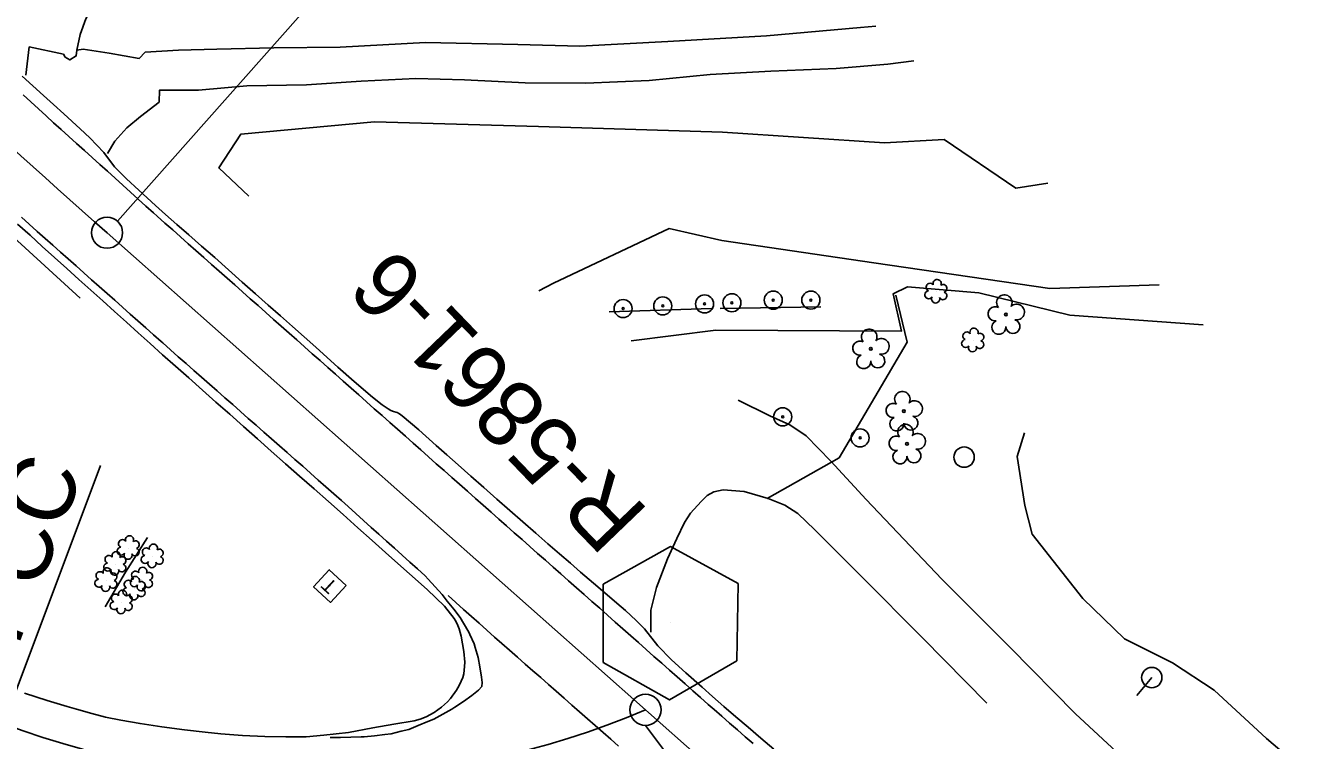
# Model space of a CAD drawing. Extents: x 474972 to 479313, y 498315 to 502691.
# Drawn here: x 476724.1 to 477032.4, y 500512.6 to 500685.1 of the extents above; entities that cross this region are included whole.
import ezdxf

# ---------------------------------------------------------------- set-up
doc = ezdxf.new("R2010")
doc.units = 0
for name, color, linetype in [('CTL Primary Horizontal and Vertical CELL', 7, 'Continuous'), ('CTL Primary Horizontal and Vertical Text', 7, 'Continuous'), ('Exist Guardrail', 7, 'Continuous'), ('Exist Horizontal Alignment', 7, 'Continuous'), ('Exist Other Culture Fence Line', 7, 'Continuous'), ('Exist Other Culture Gate', 7, 'Continuous'), ('Exist Other Culture Sign', 7, 'Continuous'), ('Exist Other Culture Sign Post CELL', 7, 'Continuous'), ('Exist Roads EOP', 7, 'Continuous'), ('Exist Roads EOP Other', 7, 'Continuous'), ('Exist Roads EOT', 7, 'Continuous'), ('Exist Roads Soil', 7, 'Continuous'), ('Exist Utilities Other Located Object CELL', 7, 'Continuous'), ('Exist Utilities Other Pole CELL', 7, 'Continuous'), ('Exist Utilities Power Pole CELL', 7, 'Continuous'), ('Exist Utilities Telephone Pedestal CELL', 7, 'Continuous'), ('Exist Vegetation Hedge Row', 7, 'Continuous'), ('Exist Vegetation Shrub CELL', 7, 'Continuous'), ('Exist Vegetation Tree CELL', 7, 'Continuous'), ('Exist Vegetation Woods Line', 7, 'Continuous')]:
    doc.layers.add(name, color=color, linetype=linetype)

msp = doc.modelspace()

# ---------------------------------------------------------------- linework, layer by layer
at = {"layer": 'CTL Primary Horizontal and Vertical CELL'}
msp.add_line((476879.52, 500540.98), (476879.52, 500540.98), dxfattribs=at)
msp.add_lwpolyline([(476863.36, 500550.34), (476879.61, 500559.4), (476895.86, 500550.46), (476895.61, 500531.84), (476879.36, 500522.4), (476863.36, 500531.46)], close=True, dxfattribs=at)
at = {"layer": 'Exist Guardrail'}
msp.add_lwpolyline([(476737.29, 500619.31), (476708.8, 500645.27), (476684.15, 500668.31), (476658.03, 500693.08), (476634.78, 500715.19), (476612.16, 500736.97), (476592.64, 500756.19), (476581.97, 500766.87)], dxfattribs=at)
at = {"layer": 'Exist Horizontal Alignment'}
for p, q in [((476746.23, 500637.93), (476820.85, 500722.08)), ((477059.47, 500355.18), (476743.74, 500635.12)), ((476720.16, 500520.15), (476742.19, 500578.94)), ((476873.56, 500516.26), (476927.6, 500444.13))]:
    msp.add_line(p, q, dxfattribs=at)
for centre in [(476743.74, 500635.12), (476873.56, 500520.01)]:
    msp.add_circle(centre, 3.75, dxfattribs=at)
for centre, radius, start, end in [((478884.49, 503049.53), 3226.8, 223.91157, 228.4381), ((476791.99, 500711.88), 208.48, 249.4634, 293.0343)]:
    msp.add_arc(centre, radius, start, end, dxfattribs=at)
at = {"layer": 'Exist Other Culture Fence Line'}
msp.add_lwpolyline([(476920.23, 500580.83), (476936.65, 500608.75), (476933.91, 500620.09)], dxfattribs=at)
at = {"layer": 'Exist Other Culture Gate'}
msp.add_line((476920.23, 500580.83), (476902.86, 500571.01), dxfattribs=at)
at = {"layer": 'Exist Other Culture Sign'}
for p, q in [((476864.78, 500616.05), (476889.45, 500616.83)), ((476891.57, 500616.86), (476915.83, 500617.21)), ((476753.54, 500561.55), (476748.22, 500553.2)), ((476748.22, 500553.2), (476743.31, 500544.89))]:
    msp.add_line(p, q, dxfattribs=at)
at = {"layer": 'Exist Other Culture Sign Post CELL'}
for centre, radius in [((476904.35, 500618.85), 2.18), ((476913.42, 500618.86), 2.18), ((476868.16, 500616.83), 2.18), ((476877.72, 500617.46), 2.18), ((476877.72, 500617.46), 0.24), ((476887.8, 500617.93), 2.18), ((476887.8, 500617.93), 0.24), ((476894.38, 500618.21), 2.18), ((476894.38, 500618.21), 0.24), ((476904.35, 500618.85), 0.24), ((476913.42, 500618.86), 0.24), ((476868.16, 500616.83), 0.24)]:
    msp.add_circle(centre, radius, dxfattribs=at)
at = {"layer": 'Exist Roads EOP'}
for points in [[(476723.29, 500672.9), (476725.87, 500670.56), (476728.4, 500668.26), (476730.87, 500666.01), (476733.3, 500663.81), (476737.27, 500660.18), (476739.56, 500658.01), (476742.97, 500654.48), (476745.57, 500651.03), (476748.47, 500648.09), (476751.4, 500645.35), (476755.44, 500641.68), (476757.87, 500639.52), (476760.57, 500637.14), (476763.48, 500634.59), (476766.53, 500631.91), (476769.71, 500629.11), (476773.03, 500626.17), (476776.36, 500623.22), (476779.55, 500620.38), (476782.62, 500617.65), (476785.56, 500615.04), (476788.42, 500612.49), (476791.25, 500609.97), (476794.05, 500607.47), (476796.82, 500605), (476799.38, 500602.72), (476803.36, 500599.21), (476807.78, 500595.45), (476810.05, 500593.58), (476811.51, 500592.6), (476812.17, 500592.26), (476812.79, 500592.01), (476813.38, 500591.83), (476813.67, 500591.72), (476814.24, 500591.42), (476814.88, 500590.98), (476818.88, 500587.55), (476823.12, 500583.79), (476825.65, 500581.55), (476828.42, 500579.09), (476831.44, 500576.42), (476834.58, 500573.64), (476837.72, 500570.87), (476840.86, 500568.1), (476844.01, 500565.34), (476847.08, 500562.65), (476850.02, 500560.09), (476852.81, 500557.66), (476855.46, 500555.36), (476857.92, 500553.24), (476862.09, 500549.66), (476866.63, 500545.77), (476868.72, 500543.95), (476871.31, 500541.58), (476873.29, 500539.54), (476876.54, 500535.49), (476879.84, 500532.08), (476883.32, 500528.92), (476887.21, 500525.47), (476889.72, 500523.25), (476892.47, 500520.85), (476895.33, 500518.36), (476898.3, 500515.8), (476901.38, 500513.16), (476904.5, 500510.49)], [(476723.88, 500524.03), (476729.31, 500522.29), (476734.12, 500520.84), (476736.35, 500520.18), (476740.06, 500519.11), (476743.39, 500518.28), (476747.09, 500517.52), (476751.71, 500516.7), (476756.92, 500515.93), (476762.39, 500515.19), (476767.41, 500514.6), (476771.19, 500514.22), (476776.38, 500513.86), (476781.81, 500513.6), (476786.83, 500513.47), (476791.74, 500513.52), (476796.04, 500513.88), (476801.98, 500514.56), (476807.79, 500515.65), (476812.87, 500516.52), (476817.82, 500517.36), (476819.26, 500517.78), (476820.68, 500518.36), (476822.57, 500519.35), (476824.35, 500520.64), (476825.85, 500521.97), (476826.56, 500522.78), (476828, 500524.8), (476828.67, 500525.91), (476829.15, 500526.92), (476829.49, 500527.85), (476829.73, 500528.71), (476829.88, 500529.57), (476829.96, 500530.5), (476829.97, 500531.53), (476829.74, 500534.1), (476829.1, 500537.77), (476828.65, 500539.53), (476828.34, 500540.37), (476827.94, 500541.22), (476827.44, 500542.08), (476825.13, 500545.03), (476820.89, 500549.05), (476816.65, 500552.85), (476813.87, 500555.33), (476810.87, 500558.01), (476807.64, 500560.89), (476804.19, 500563.96), (476800.64, 500567.12), (476797.12, 500570.24), (476793.64, 500573.32), (476790.18, 500576.38), (476786.75, 500579.4), (476783.35, 500582.41), (476779.98, 500585.39), (476776.63, 500588.36), (476773.31, 500591.31), (476770.01, 500594.24), (476766.72, 500597.16), (476763.45, 500600.07), (476760.24, 500602.92), (476757.14, 500605.69), (476754.14, 500608.38), (476751.25, 500610.98), (476748.41, 500613.55), (476745.56, 500616.12), (476742.7, 500618.7), (476739.83, 500621.28), (476736.94, 500623.87), (476734.03, 500626.49), (476731.1, 500629.14), (476728.14, 500631.82), (476725.18, 500634.51), (476722.2, 500637.21)]]:
    msp.add_lwpolyline(points, dxfattribs=at)
at = {"layer": 'Exist Roads EOP Other'}
for points in [[(476929.08, 500684.95), (476925.41, 500684.62), (476902.71, 500682.62), (476878.93, 500681.21), (476857.73, 500680.14), (476842.79, 500680.49), (476820.55, 500681), (476799.91, 500679.85), (476783.96, 500679.68), (476770.19, 500679.43), (476760.96, 500679.12), (476752.95, 500678.68), (476751.52, 500677.16), (476744.23, 500678.4), (476737.96, 500679.38), (476736.47, 500679.15), (476736.33, 500677.78), (476734.77, 500676.8), (476733.63, 500677.5), (476733.21, 500678.21), (476725, 500679.94), (476724.18, 500673.12)], [(476743.87, 500654.23), (476745.61, 500657.23), (476748.5, 500660.39), (476751.8, 500663.18), (476756.29, 500666.63), (476756.39, 500669.5), (476765.79, 500669.53), (476777.47, 500670.54), (476791.84, 500670.82), (476804.98, 500671.7), (476818.16, 500672.36), (476829.93, 500672.03), (476844.55, 500671.31), (476859.15, 500671.2), (476874.43, 500671.87), (476889.12, 500673.29), (476903.78, 500674.12), (476919.55, 500674.76), (476931.95, 500675.77), (476938.26, 500676.57)]]:
    msp.add_lwpolyline(points, dxfattribs=at)
at = {"layer": 'Exist Roads EOT'}
for points in [[(476899.48, 500511.89), (476897.6, 500513.53), (476895.72, 500515.18), (476893.84, 500516.82), (476891.96, 500518.47), (476890.08, 500520.11), (476888.7, 500521.32), (476886.82, 500522.97), (476884.95, 500524.63), (476883.08, 500526.29), (476881.21, 500527.94), (476879.34, 500529.6), (476877.47, 500531.26), (476875.6, 500532.91), (476873.73, 500534.57), (476871.86, 500536.23), (476869.99, 500537.88), (476868.12, 500539.54), (476866.25, 500541.2), (476864.38, 500542.85), (476862.51, 500544.51), (476860.64, 500546.17), (476858.76, 500547.83), (476856.89, 500549.48), (476855.02, 500551.14), (476853.15, 500552.8), (476851.28, 500554.45), (476849.41, 500556.11), (476847.54, 500557.77), (476845.67, 500559.42), (476843.8, 500561.08), (476841.93, 500562.74), (476840.06, 500564.39), (476838.19, 500566.05), (476836.32, 500567.71), (476834.45, 500569.36), (476832.58, 500571.02), (476830.7, 500572.68), (476830.61, 500572.76), (476828.74, 500574.42), (476826.87, 500576.08), (476825, 500577.74), (476823.13, 500579.4), (476821.27, 500581.05), (476819.4, 500582.71), (476817.53, 500584.37), (476815.66, 500586.03), (476813.79, 500587.69), (476811.92, 500589.35), (476810.05, 500591), (476808.18, 500592.66), (476806.31, 500594.32), (476804.44, 500595.98), (476802.57, 500597.64), (476800.7, 500599.3), (476798.83, 500600.96), (476796.97, 500602.61), (476795.1, 500604.27), (476793.23, 500605.93), (476791.36, 500607.59), (476789.49, 500609.25), (476787.62, 500610.91), (476785.75, 500612.56), (476783.88, 500614.22), (476782.01, 500615.88), (476780.14, 500617.54), (476778.27, 500619.2), (476776.4, 500620.86), (476774.53, 500622.52), (476772.67, 500624.17), (476770.8, 500625.83), (476768.93, 500627.49), (476767.06, 500629.15), (476765.19, 500630.81), (476763.32, 500632.47), (476761.45, 500634.13), (476759.58, 500635.78), (476757.71, 500637.44), (476755.84, 500639.1), (476754.97, 500639.88), (476753.11, 500641.55), (476751.26, 500643.23), (476749.4, 500644.9), (476747.55, 500646.58), (476745.69, 500648.25), (476743.84, 500649.93), (476741.99, 500651.6), (476740.13, 500653.28), (476738.28, 500654.95), (476736.42, 500656.63), (476734.57, 500658.3), (476732.71, 500659.98), (476730.86, 500661.66), (476729.04, 500663.3), (476727.2, 500665), (476725.37, 500666.7), (476723.53, 500668.39)], [(476797.57, 500513.33), (476800.06, 500513.37), (476802.54, 500513.42), (476805.02, 500513.47), (476805.76, 500513.48), (476808.23, 500513.77), (476810.69, 500514.05), (476812.23, 500514.23), (476814.64, 500514.84), (476816.47, 500515.3), (476818.77, 500516.24), (476821.07, 500517.18), (476822.52, 500517.77), (476824.69, 500518.98), (476826.86, 500520.19), (476827.63, 500520.62), (476829.67, 500522.05), (476831.66, 500523.45), (476833.27, 500524.73), (476834.09, 500525.64), (476834.21, 500526.59), (476834, 500527.9), (476833.58, 500530.35), (476833.19, 500532.65), (476832.48, 500535.05), (476832.22, 500535.91), (476831.22, 500538.2), (476830.97, 500538.78), (476829.69, 500540.93), (476828.85, 500542.33), (476827.32, 500544.3), (476825.78, 500546.27), (476824.55, 500547.86), (476822.86, 500549.7), (476821.16, 500551.53), (476820.44, 500552.33), (476818.58, 500554), (476816.72, 500555.67), (476814.87, 500557.34), (476813.01, 500559.02), (476811.15, 500560.69), (476809.3, 500562.36), (476807.44, 500564.04), (476805.59, 500565.71), (476803.73, 500567.38), (476801.87, 500569.06), (476800.28, 500570.49), (476798.41, 500572.14), (476796.53, 500573.8), (476794.66, 500575.45), (476792.79, 500577.1), (476790.91, 500578.76), (476789.04, 500580.41), (476787.16, 500582.06), (476785.29, 500583.72), (476783.42, 500585.37), (476781.54, 500587.02), (476779.67, 500588.68), (476777.79, 500590.33), (476775.92, 500591.98), (476774.05, 500593.64), (476772.17, 500595.29), (476770.3, 500596.94), (476768.42, 500598.6), (476766.55, 500600.25), (476764.68, 500601.9), (476762.8, 500603.56), (476760.93, 500605.21), (476759.05, 500606.86), (476757.18, 500608.52), (476756.81, 500608.84), (476754.95, 500610.5), (476753.08, 500612.16), (476751.21, 500613.82), (476749.35, 500615.49), (476747.48, 500617.15), (476745.61, 500618.81), (476743.74, 500620.47), (476741.88, 500622.13), (476740.01, 500623.79), (476738.14, 500625.46), (476736.27, 500627.12), (476734.41, 500628.78), (476732.54, 500630.44), (476730.67, 500632.1), (476728.81, 500633.76), (476726.94, 500635.43), (476726.83, 500635.53), (476724.98, 500637.21), (476723.12, 500638.89)], [(476825.99, 500547.56), (476827.85, 500545.9), (476829.72, 500544.23), (476831.58, 500542.57), (476833.45, 500540.9), (476835.31, 500539.24), (476837.17, 500537.57), (476838.91, 500536.02), (476840.79, 500534.37), (476842.66, 500532.72), (476844.54, 500531.07), (476846.42, 500529.43), (476848.3, 500527.78), (476850.17, 500526.13), (476852.05, 500524.48), (476853.93, 500522.83), (476855.81, 500521.18), (476857.68, 500519.53), (476859.56, 500517.88), (476861.44, 500516.23), (476863.32, 500514.58), (476865.19, 500512.94), (476867.07, 500511.29)]]:
    msp.add_lwpolyline(points, dxfattribs=at)
at = {"layer": 'Exist Roads Soil'}
for points in [[(476828.22, 500777.12), (476817.81, 500765.72), (476802.57, 500751.63), (476787.45, 500738.39), (476765.65, 500718.95), (476752.83, 500706.5), (476744.7, 500697.39), (476741.41, 500691.69), (476738.61, 500686.71), (476737.29, 500682.92), (476736.47, 500679.15)], [(476992.54, 500504.83), (476977.24, 500519.05), (476961.36, 500535.12), (476945, 500551.52), (476926.76, 500570.74), (476918.24, 500579.99), (476912.29, 500586.13), (476908.35, 500588.81), (476903.53, 500590.92), (476895.89, 500594.7)], [(476964.89, 500586.81), (476963.19, 500581.17), (476965, 500569.32), (476966.77, 500562.4), (476978.98, 500546.89), (476989.03, 500537.17), (477000.62, 500531.37), (477010.68, 500524.79), (477023.27, 500513.12), (477026.47, 500510.38)], [(476874.81, 500538.77), (476874.86, 500544.08), (476876.21, 500549.54), (476878.89, 500556.42), (476881.1, 500561.31), (476882.98, 500565.23), (476884.42, 500567.43), (476886.97, 500570.24), (476888.42, 500571.72), (476890.05, 500572.64), (476892.27, 500573.07), (476897.36, 500572.65), (476903.12, 500570.96), (476907.14, 500569.42), (476910.29, 500567.4), (476914.37, 500563.43), (476925.53, 500552.24), (476940.41, 500537.28), (476955.83, 500521.6)]]:
    msp.add_lwpolyline(points, dxfattribs=at)
at = {"layer": 'Exist Utilities Other Located Object CELL'}
for centre, radius in [((476906.63, 500590.7), 2.18), ((476906.63, 500590.7), 0.24), ((476925.3, 500585.62), 2.18), ((476925.3, 500585.62), 0.24)]:
    msp.add_circle(centre, radius, dxfattribs=at)
at = {"layer": 'Exist Utilities Other Pole CELL'}
msp.add_circle((476950.37, 500580.98), 2.46, dxfattribs=at)
at = {"layer": 'Exist Utilities Power Pole CELL'}
for q in [(476992, 500523.49), (476995.62, 500527.79)]:
    msp.add_line((476995.62, 500527.79), q, dxfattribs=at)
msp.add_circle((476995.62, 500527.79), 2.45, dxfattribs=at)
at = {"layer": 'Exist Utilities Telephone Pedestal CELL'}
msp.add_line((476797.51, 500549.8), (476797.51, 500549.8), dxfattribs=at)
msp.add_lwpolyline([(476801.43, 500550.02), (476797.33, 500553.83), (476793.52, 500549.72), (476797.63, 500545.92), (476801.43, 500550.02)], dxfattribs=at)
at = {"layer": 'Exist Vegetation Hedge Row'}
msp.add_lwpolyline([(477007.98, 500612.86), (476975.89, 500615.2), (476953.89, 500620.65), (476936.72, 500622.03), (476933.29, 500620.41), (476935.28, 500611.37), (476890.54, 500611.61), (476870.1, 500609)], dxfattribs=at)
at = {"layer": 'Exist Vegetation Shrub CELL'}
for p, q in [((476943.64, 500620.82), (476943.64, 500620.82)), ((476952.52, 500609.07), (476952.52, 500609.07)), ((476748.94, 500558.99), (476748.94, 500558.99)), ((476754.71, 500556.98), (476754.71, 500556.98)), ((476745.72, 500555.16), (476745.72, 500555.16)), ((476743.54, 500551.25), (476743.54, 500551.25)), ((476752.11, 500551.38), (476752.11, 500551.38)), ((476750.34, 500549.18), (476750.34, 500549.18)), ((476747.24, 500545.86), (476747.24, 500545.86))]:
    msp.add_line(p, q, dxfattribs=at)
for centre, radius, start, end in [((476943.87, 500622.86), 0.99, 334.8391, 200.4717), ((476941.84, 500620.12), 0.955, 95.1099, 327.9534), ((476942.16, 500621.95), 0.968, 35.8908, 245.4216), ((476945.28, 500619.89), 0.937, 204.9913, 73.4601), ((476945.31, 500621.69), 0.929, 284.4567, 126.0861), ((476943.51, 500619.14), 0.984, 151.2797, 21.387), ((476952.75, 500611.11), 0.99, 334.8391, 200.4717), ((476950.72, 500608.37), 0.955, 95.1099, 327.9534), ((476951.04, 500610.2), 0.968, 35.8908, 245.4216), ((476954.16, 500608.14), 0.937, 204.9913, 73.4601), ((476954.19, 500609.94), 0.929, 284.4567, 126.0861), ((476952.39, 500607.39), 0.984, 151.2797, 21.387), ((476749.17, 500561.03), 0.99, 334.8391, 200.4717), ((476747.14, 500558.29), 0.955, 95.1099, 327.9534), ((476747.46, 500560.12), 0.968, 35.8908, 245.4216), ((476750.58, 500558.06), 0.937, 204.9913, 73.4601), ((476750.61, 500559.86), 0.929, 284.4567, 126.0861), ((476753.22, 500558.1), 0.968, 35.8908, 245.4216), ((476754.93, 500559.02), 0.99, 334.8391, 200.4717), ((476744.23, 500556.29), 0.968, 35.8908, 245.4216), ((476745.94, 500557.2), 0.99, 334.8391, 200.4717), ((476747.39, 500556.03), 0.929, 284.4567, 126.0861), ((476748.81, 500557.31), 0.984, 151.2797, 21.387), ((476752.91, 500556.27), 0.955, 95.1099, 327.9534), ((476756.34, 500556.05), 0.937, 204.9913, 73.4601), ((476756.38, 500557.84), 0.929, 284.4567, 126.0861), ((476742.06, 500552.38), 0.968, 35.8908, 245.4216), ((476743.77, 500553.29), 0.99, 334.8391, 200.4717), ((476743.92, 500554.46), 0.955, 95.1099, 327.9534), ((476745.59, 500553.48), 0.984, 151.2797, 21.387), ((476745.21, 500552.12), 0.929, 284.4567, 126.0861), ((476747.35, 500554.24), 0.937, 204.9913, 73.4601), ((476750.63, 500552.51), 0.968, 35.8908, 245.4216), ((476752.34, 500553.43), 0.99, 334.8391, 200.4717), ((476753.78, 500552.25), 0.929, 284.4567, 126.0861), ((476754.58, 500555.29), 0.984, 151.2797, 21.387), ((476741.74, 500550.55), 0.955, 95.1099, 327.9534), ((476743.41, 500549.57), 0.984, 151.2797, 21.387), ((476745.18, 500550.32), 0.937, 204.9913, 73.4601), ((476748.85, 500550.31), 0.968, 35.8908, 245.4216), ((476750.31, 500550.68), 0.955, 95.1099, 327.9534), ((476750.57, 500551.22), 0.99, 334.8391, 200.4717), ((476751.98, 500549.7), 0.984, 151.2797, 21.387), ((476752.01, 500550.05), 0.929, 284.4567, 126.0861), ((476753.75, 500550.46), 0.937, 204.9913, 73.4601), ((476745.76, 500546.99), 0.968, 35.8908, 245.4216), ((476747.47, 500547.9), 0.99, 334.8391, 200.4717), ((476748.54, 500548.48), 0.955, 95.1099, 327.9534), ((476748.91, 500546.73), 0.929, 284.4567, 126.0861), ((476750.21, 500547.5), 0.984, 151.2797, 21.387), ((476751.97, 500548.26), 0.937, 204.9913, 73.4601), ((476745.44, 500545.16), 0.955, 95.1099, 327.9534), ((476747.11, 500544.18), 0.984, 151.2797, 21.387), ((476748.88, 500544.93), 0.937, 204.9913, 73.4601)]:
    msp.add_arc(centre, radius, start, end, dxfattribs=at)
at = {"layer": 'Exist Vegetation Tree CELL'}
for p, q in [((476960.46, 500615.4), (476960.46, 500615.4)), ((476927.86, 500607.12), (476927.86, 500607.12)), ((476935.86, 500592.09), (476935.86, 500592.09)), ((476936.6, 500584.17), (476936.6, 500584.17))]:
    msp.add_line(p, q, dxfattribs=at)
for centre in [(476960.46, 500615.4), (476927.86, 500607.12), (476935.86, 500592.09), (476936.6, 500584.17)]:
    msp.add_circle(centre, 0.326, dxfattribs=at)
for centre, radius, start, end in [((476960.07, 500618.27), 1.86, 330.1651, 219.7134), ((476963, 500615.99), 1.9, 257.1011, 134.1999), ((476957.85, 500615.55), 1.73, 62.6636, 279.3457), ((476927.48, 500610), 1.86, 330.1651, 219.7134), ((476958.75, 500612.28), 1.69, 111.5671, 6.231), ((476962.13, 500612.5), 1.7, 181.2822, 74.56), ((476925.26, 500607.28), 1.73, 62.6636, 279.3457), ((476930.41, 500607.71), 1.9, 257.1011, 134.1999), ((476926.16, 500604), 1.69, 111.5671, 6.231), ((476929.54, 500604.22), 1.7, 181.2822, 74.56), ((476935.47, 500594.96), 1.86, 330.1651, 219.7134), ((476933.25, 500592.24), 1.73, 62.6636, 279.3457), ((476938.41, 500592.68), 1.9, 257.1011, 134.1999), ((476934.15, 500588.97), 1.69, 111.5671, 6.231), ((476937.53, 500589.19), 1.7, 181.2822, 74.56), ((476936.22, 500587.04), 1.86, 330.1651, 219.7134), ((476939.15, 500584.76), 1.9, 257.1011, 134.1999), ((476933.99, 500584.32), 1.73, 62.6636, 279.3457), ((476934.9, 500581.05), 1.69, 111.5671, 6.231), ((476938.27, 500581.27), 1.7, 181.2822, 74.56)]:
    msp.add_arc(centre, radius, start, end, dxfattribs=at)
at = {"layer": 'Exist Vegetation Woods Line'}
for points in [[(476777.89, 500643.95), (476770.69, 500650.74), (476776.03, 500658.91), (476808.23, 500661.83), (476847.79, 500660.77), (476892.08, 500659.4), (476931.15, 500656.77), (476945.58, 500657.59), (476962.81, 500645.87), (476970.52, 500647.09)], [(476997.42, 500622.51), (476971.03, 500621.67), (476928.58, 500627.82), (476891.97, 500633.21), (476879.29, 500636.13), (476851.35, 500622.98), (476847.81, 500621.12)]]:
    msp.add_lwpolyline(points, dxfattribs=at)

# ---------------------------------------------------------------- texts
at = {"layer": 'CTL Primary Horizontal and Vertical Text'}
msp.add_text('R-5861-6', height=16, rotation=133.908, dxfattribs=at).set_placement((476874.69, 500567.82))
at = {"layer": 'Exist Horizontal Alignment'}
msp.add_text('PCC', height=16, rotation=69.4634, dxfattribs=at).set_placement((476722.25, 500535.1))
at = {"layer": 'Exist Utilities Telephone Pedestal CELL'}
msp.add_text('T', height=3.42, rotation=137.1675, dxfattribs=at).set_placement((476799.5, 500550.29))

doc.saveas('drawing.dxf')
